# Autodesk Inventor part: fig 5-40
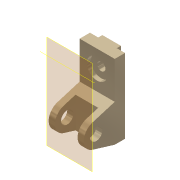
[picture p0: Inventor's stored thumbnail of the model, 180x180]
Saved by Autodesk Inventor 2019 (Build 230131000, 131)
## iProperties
Shininess: 65.0
Angle Display Precision: 2
Document Length Units: 11269
Document Angle Units: 11279
Document Time Units: 11290
Document Mass Units: 11283
Document Length Units Precision: 3
Document Angle Units Precision: 2
Created: 2001-11
Part Number: fig 5-40
Document SubType Name: Modeling
Designer: Renu Muthoo
Density: 1 g/cm^3
Material: Generic
Appearance: Metal-Titanium (Polished)
Density: 0.0
Volumn: 0.0
Area: 0.0
PropertySet Name: Model Information
Control State: 0
Master: False
Checked Out: False
Author: Renu Muthoo
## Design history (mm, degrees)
node "Sketch1"
sketch "Sketch2"
  geometry: L1 (33.257, 104.664)-(33.257, -75.336); L2 (33.257, -75.336)-(8.257, -75.336); L3 (8.257, -75.336)-(-45.451, -59.045); L4 (-45.451, -1.628)-(8.257, 14.664); L5 (8.257, 14.664)-(8.257, 104.664); L6 (8.257, 104.664)-(33.257, 104.664); C1 r 15 at (-36.743, -30.336); A1 r 30 centre (-36.743, -30.336) between (-45.451, -1.628) and (-45.451, -59.045)
  constraints: 12 end point, 2 centre point, 2 equal length, 2 parallel, 2 point on circle, 2 tangent, 1 coincident, 1 perpendicular, 1 vertical
  dimensions: "d0" = 180 distance of L1.start L1.end; "d1" = 30 radius of A1; "d2" = 25 distance of L5.end L1.start; "d3" = 45 distance from line of L2 A1.centre; "d4" = 70 distance from line of L1 A1.centre; "d5" = 30 diameter of C1
extrude "Extrusion1" new body sketch "Sketch2" distance "d6" = 85; taper "d7" = 0 deg
workplane "Work Plane1"
sketch "Sketch3"
  geometry: L1 (15, 62.364)-(70, 62.364); L2 (70, 62.364)-(70, -52.386); L3 (70, -52.386)-(15, -52.386); L4 (15, -52.386)-(15, 62.364); L5 (0, -45)-(0, -28.708) reference
  constraints: 8 end point, 2 parallel, 1 horizontal, 1 perpendicular
  dimensions: "d8" = 55 distance of L1.start L1.end; "d9" = 15 distance between parallel lines of L5 L4
extrude "Extrusion2" cut sketch "Sketch3" distance "d10" = 50; taper "d11" = 0 deg
sketch "Sketch4"
  geometry: L1 (0, 25)-(85, 25) reference; L2 (0, 0)-(0, 25) reference; L3 (20, 25)-(65, 25); L4 (65, 25)-(65, 35); L5 (65, 35)-(20, 35); L6 (20, 35)-(20, 25)
  constraints: 8 end point, 2 parallel, 1 horizontal, 1 perpendicular, 1 point on line
  dimensions: "d12" = 45 distance of L4.end L5.end; "d13" = 10 distance of L3.end L4.end; "d14" = 20 distance between parallel lines of L2 L6
extrude "Extrusion3" join sketch "Sketch4" stored distance "d15" = 50; taper "d16" = 0 deg
sketch "Sketch5"
  geometry: L1 (85, 0)-(85, 90) reference; L2 (0, 90)-(85, 90) reference; 1 further point
  dimensions: "d17" = 42 distance from line of L2 point (42.5, 48); "d18" = 42.5 distance from line of L1 point (42.5, 48)
hole "Hole1" sketch "Sketch5" at (42.5, 48) diameter "d19" = 20; stored, may be unused: countersink angle "d23" = 82 deg, drill point angle "d25" = 118 deg; dims "d20" = 6, "d21" = 50, "d22" = 10, "d24" = 8
workaxis "Work Axis1"
  workplane "Work Plane3"
body "Solid1"
